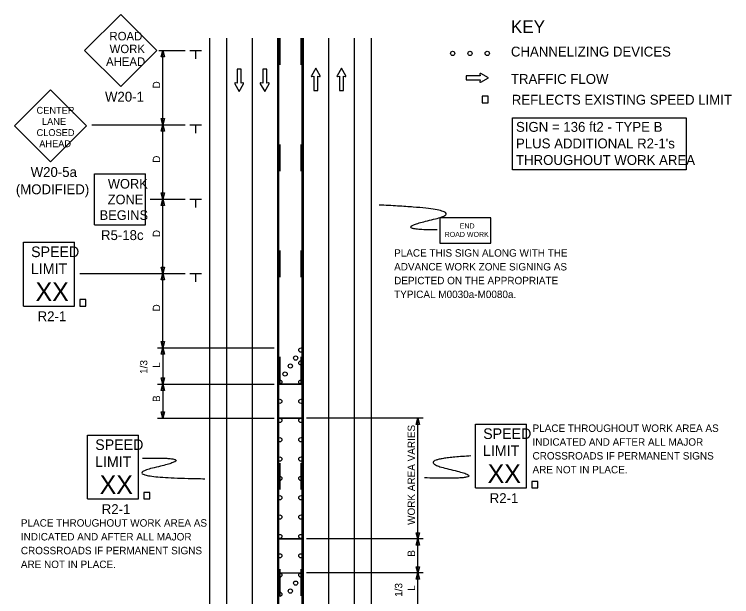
# Model space of a CAD drawing. Extents: x 16739 to 18482, y 7218 to 8206.
# Drawn here: x 16739 to 17415, y 7658 to 8206 of the extents above; entities that cross this region are included whole.
import ezdxf

# ---------------------------------------------------------------- set-up
doc = ezdxf.new("R2010")
doc.units = 0
for name, color, linetype in [('ALI_LEGAL_EX', 7, 'Continuous'), ('MT_SCRATCH_LEVEL_E', 7, 'Continuous'), ('PAVT_EDGE_EX', 7, 'Continuous'), ('TRAFFIC_SIGNS_PR', 7, 'Continuous'), ('TYPICAL_TEXT_DIMEN_EX', 7, 'Continuous'), ('TYPICAL_TEXT_DIMEN_PR', 7, 'Continuous')]:
    doc.layers.add(name, color=color, linetype=linetype)

msp = doc.modelspace()

# ---------------------------------------------------------------- linework, layer by layer
at = {"layer": 'ALI_LEGAL_EX'}
for points in [[(16963.15, 8183.87), (16963.15, 8158.87)], [(17035.15, 8183.87), (17035.15, 8158.87)], [(16963.15, 8083.87), (16963.15, 8058.87)], [(17035.15, 8083.87), (17035.15, 8058.87)], [(16963.15, 7983.87), (16963.15, 7958.87)], [(17035.15, 7983.87), (17035.15, 7958.87)], [(16963.15, 7883.87), (16963.15, 7858.87)], [(17035.15, 7883.87), (17035.15, 7858.87)], [(16963.15, 7783.87), (16963.15, 7758.87)], [(17035.15, 7783.87), (17035.15, 7758.87)], [(16963.15, 7683.87), (16963.15, 7658.87)], [(17035.15, 7683.87), (17035.15, 7658.87)]]:
    msp.add_lwpolyline(points, dxfattribs=at)
at = {"layer": 'MT_SCRATCH_LEVEL_E'}
for p, q in [((16952.82, 8154.76), (16949.08, 8154.76)), ((16949.08, 8154.76), (16949.08, 8141.5)), ((16952.82, 8154.76), (16949.08, 8154.76)), ((16949.08, 8154.76), (16949.08, 8141.5)), ((16952.82, 8141.5), (16952.82, 8154.76)), ((16952.82, 8141.5), (16952.82, 8154.76)), ((16976.89, 8154.76), (16973.15, 8154.76)), ((16973.15, 8154.76), (16973.15, 8141.5)), ((16976.89, 8154.76), (16973.15, 8154.76)), ((16973.15, 8154.76), (16973.15, 8141.5)), ((16976.89, 8141.5), (16976.89, 8154.76)), ((16976.89, 8141.5), (16976.89, 8154.76)), ((17023.09, 8155.7), (17018.98, 8148.46)), ((17023.09, 8155.7), (17018.98, 8148.46)), ((17027.24, 8148.46), (17023.09, 8155.7)), ((17027.24, 8148.46), (17023.09, 8155.7)), ((17047.26, 8155.7), (17043.15, 8148.46)), ((17047.26, 8155.7), (17043.15, 8148.46)), ((17051.4, 8148.46), (17047.26, 8155.7)), ((17051.4, 8148.46), (17047.26, 8155.7)), ((17019.46, 8147.78), (17021.24, 8148.1)), ((17019.46, 8147.78), (17021.24, 8148.1)), ((17021.24, 8148.1), (17021.24, 8134.84)), ((17021.24, 8148.1), (17021.24, 8134.84)), ((17024.98, 8134.84), (17024.98, 8148.1)), ((17024.98, 8148.1), (17026.76, 8147.78)), ((17024.98, 8134.84), (17024.98, 8148.1)), ((17024.98, 8148.1), (17026.76, 8147.78)), ((17043.63, 8147.78), (17045.41, 8148.1)), ((17043.63, 8147.78), (17045.41, 8148.1)), ((17045.41, 8148.1), (17045.41, 8134.84)), ((17045.41, 8148.1), (17045.41, 8134.84)), ((17049.15, 8134.84), (17049.15, 8148.1)), ((17049.15, 8148.1), (17050.93, 8147.78)), ((17049.15, 8134.84), (17049.15, 8148.1)), ((17049.15, 8148.1), (17050.93, 8147.78)), ((17178.02, 8148.4), (17164.76, 8148.4)), ((17164.76, 8148.4), (17164.76, 8144.66)), ((17178.02, 8148.4), (17164.76, 8148.4)), ((17164.76, 8148.4), (17164.76, 8144.66)), ((17177.7, 8150.17), (17178.02, 8148.4)), ((17177.7, 8150.17), (17178.02, 8148.4)), ((17185.63, 8146.55), (17178.39, 8150.66)), ((17185.63, 8146.55), (17178.39, 8150.66)), ((17178.39, 8142.4), (17185.63, 8146.55)), ((17178.39, 8142.4), (17185.63, 8146.55)), ((16946.82, 8141.13), (16950.97, 8133.89)), ((16946.82, 8141.13), (16950.97, 8133.89)), ((16949.08, 8141.5), (16947.3, 8141.82)), ((16949.08, 8141.5), (16947.3, 8141.82)), ((16950.97, 8133.89), (16955.08, 8141.13)), ((16950.97, 8133.89), (16955.08, 8141.13)), ((16954.6, 8141.82), (16952.82, 8141.5)), ((16954.6, 8141.82), (16952.82, 8141.5)), ((16970.9, 8141.13), (16975.04, 8133.89)), ((16970.9, 8141.13), (16975.04, 8133.89)), ((16973.15, 8141.5), (16971.37, 8141.82)), ((16973.15, 8141.5), (16971.37, 8141.82)), ((16975.04, 8133.89), (16979.15, 8141.13)), ((16975.04, 8133.89), (16979.15, 8141.13)), ((16978.67, 8141.82), (16976.89, 8141.5)), ((16978.67, 8141.82), (16976.89, 8141.5)), ((17164.76, 8144.66), (17178.02, 8144.66)), ((17164.76, 8144.66), (17178.02, 8144.66)), ((17178.02, 8144.66), (17177.7, 8142.88)), ((17178.02, 8144.66), (17177.7, 8142.88)), ((17021.24, 8134.84), (17024.98, 8134.84)), ((17021.24, 8134.84), (17024.98, 8134.84)), ((17045.41, 8134.84), (17049.15, 8134.84)), ((17045.41, 8134.84), (17049.15, 8134.84))]:
    msp.add_line(p, q, dxfattribs=at)
for centre, start, end in [((17019.38, 8148.24), 150.42484, 279.96381), ((17019.38, 8148.24), 150.42484, 279.96381), ((17026.83, 8148.24), 260.03619, 29.77312), ((17026.83, 8148.24), 260.03619, 29.77312), ((17043.55, 8148.24), 150.42484, 279.96381), ((17043.55, 8148.24), 150.42484, 279.96381), ((17051, 8148.24), 260.03619, 29.77312), ((17051, 8148.24), 260.03619, 29.77312), ((17178.16, 8150.25), 60.42484, 189.96381), ((17178.16, 8150.25), 60.42484, 189.96381), ((16947.23, 8141.36), 80.03619, 209.77312), ((16947.23, 8141.36), 80.03619, 209.77312), ((16954.67, 8141.36), 330.42484, 99.96381), ((16954.67, 8141.36), 330.42484, 99.96381), ((16971.3, 8141.36), 80.03619, 209.77312), ((16971.3, 8141.36), 80.03619, 209.77312), ((16978.75, 8141.36), 330.42484, 99.96381), ((16978.75, 8141.36), 330.42484, 99.96381), ((17178.16, 8142.81), 170.03619, 299.77312), ((17178.16, 8142.81), 170.03619, 299.77312)]:
    msp.add_arc(centre, 0.463, start, end, dxfattribs=at)
at = {"layer": 'PAVT_EDGE_EX'}
for p, q in [((16923.15, 8183.87), (16923.15, 7354.69)), ((16939.15, 8183.87), (16939.15, 7354.69)), ((16963.15, 8183.87), (16963.15, 7354.69)), ((16987.15, 8183.87), (16987.15, 7354.69)), ((16988.15, 8183.87), (16988.15, 7354.69)), ((17010.15, 8183.87), (17010.15, 7354.69)), ((17011.15, 8183.87), (17011.15, 7354.69)), ((17035.15, 8183.87), (17035.15, 7354.69)), ((17059.15, 8183.87), (17059.15, 7354.69)), ((17075.15, 8183.87), (17075.15, 7354.69)), ((16987.15, 7858.2), (17011.15, 7858.2)), ((17011.15, 7858.2), (16987.15, 7858.2)), ((16987.15, 7858.2), (16987.15, 7826.14)), ((17011.15, 7826.14), (17011.15, 7858.2)), ((17011.15, 7826.14), (16987.15, 7826.14)), ((16987.15, 7826.14), (16987.15, 7712.42)), ((16987.15, 7826.14), (17011.15, 7826.14)), ((16987.15, 7826.14), (17011.15, 7826.14)), ((16987.15, 7826.14), (17011.15, 7826.14)), ((17011.15, 7712.42), (17011.15, 7826.14)), ((16987.15, 7712.42), (17011.15, 7712.42)), ((16987.15, 7712.42), (17011.15, 7712.42)), ((17011.15, 7712.42), (16987.15, 7712.42)), ((16987.15, 7712.42), (16987.15, 7680.36)), ((17011.15, 7680.36), (17011.15, 7712.42)), ((16987.15, 7680.36), (17011.15, 7680.36)), ((16987.15, 7680.36), (17011.15, 7680.36))]:
    msp.add_line(p, q, dxfattribs=at)
for points in [[(16989.15, 8183.87), (16989.15, 8158.87)], [(17009.15, 8183.87), (17009.15, 8158.87)], [(16989.15, 8083.87), (16989.15, 8058.87)], [(17009.15, 8083.87), (17009.15, 8058.87)], [(16989.15, 7983.87), (16989.15, 7958.87)], [(17009.15, 7983.87), (17009.15, 7958.87)], [(16989.15, 7883.87), (16989.15, 7858.87)], [(17009.15, 7883.87), (17009.15, 7858.87)], [(16989.15, 7783.87), (16989.15, 7758.87)], [(17009.15, 7783.87), (17009.15, 7758.87)], [(16989.15, 7683.87), (16989.15, 7658.87)], [(17009.15, 7683.87), (17009.15, 7658.87)]]:
    msp.add_lwpolyline(points, dxfattribs=at)
at = {"layer": 'TRAFFIC_SIGNS_PR'}
for p, q in [((16839.46, 8206.42), (16805.51, 8172.48)), ((16873.4, 8172.48), (16839.46, 8206.42)), ((16805.51, 8172.48), (16839.46, 8138.54)), ((16839.46, 8138.54), (16873.4, 8172.48)), ((16773.26, 8135.48), (16739.32, 8101.54)), ((16807.2, 8101.54), (16773.26, 8135.48)), ((16739.32, 8101.54), (16773.26, 8067.59)), ((16773.26, 8067.59), (16807.2, 8101.54)), ((16814.89, 8008.16), (16814.89, 8056.16)), ((16814.89, 8056.16), (16862.89, 8056.16)), ((16862.89, 8008.16), (16862.89, 8056.16)), ((16814.89, 8008.16), (16862.89, 8008.16)), ((16747.89, 7991.73), (16795.89, 7991.73)), ((16747.89, 7931.73), (16747.89, 7991.73)), ((16795.89, 7931.73), (16795.89, 7991.73)), ((16747.89, 7931.73), (16795.89, 7931.73)), ((17173.54, 7820.47), (17221.54, 7820.47)), ((17173.54, 7760.47), (17173.54, 7820.47)), ((17221.54, 7760.47), (17221.54, 7820.47)), ((16808.27, 7810.1), (16856.27, 7810.1)), ((16808.27, 7750.1), (16808.27, 7810.1)), ((16856.27, 7750.1), (16856.27, 7810.1)), ((17173.54, 7760.47), (17221.54, 7760.47)), ((16808.27, 7750.1), (16856.27, 7750.1))]:
    msp.add_line(p, q, dxfattribs=at)
for points in [[(17179.71, 8123.17), (17185.3, 8123.17), (17185.3, 8129.34), (17179.71, 8129.34)], [(17139.95, 7990.83), (17187.95, 7990.83), (17187.95, 8014.83), (17139.95, 8014.83)], [(16800.9, 7931.73), (16806.5, 7931.73), (16806.5, 7937.9), (16800.9, 7937.9)], [(17226.56, 7760.47), (17232.15, 7760.47), (17232.15, 7766.64), (17226.56, 7766.64)], [(16861.28, 7750.1), (16866.88, 7750.1), (16866.88, 7756.28), (16861.28, 7756.28)]]:
    msp.add_lwpolyline(points, close=True, dxfattribs=at)
for centre in [(17152, 8169.65), (17168.3, 8169.65), (17184.6, 8169.65), (17009.13, 7890.24), (17004.16, 7882.72), (16999.19, 7875.22), (17009.13, 7878.21), (16994.22, 7867.72), (16989.25, 7860.21), (17009.13, 7860.21), (16989.25, 7842.02), (17009.13, 7842.02), (16989.25, 7824.02), (17009.13, 7824.02), (16989.25, 7805.81), (17009.13, 7805.81), (16989.25, 7787.59), (17009.13, 7787.59), (16989.25, 7769.38), (17009.13, 7769.38), (16989.25, 7751.16), (17009.13, 7751.16), (16989.25, 7732.95), (17009.13, 7732.95), (16989.25, 7714.73), (17009.13, 7714.73), (16989.25, 7696.52), (17009.13, 7696.52), (16989.25, 7678.31), (17009.13, 7678.31), (17004.16, 7670.79), (16989.25, 7660.31), (16999.19, 7663.29)]:
    msp.add_circle(centre, 2, dxfattribs=at)
for points in [[(17137.31, 8003.38), (17090.07, 8003.38), (17175.09, 8022.73), (17082.79, 8026.8)], [(16859.89, 7788.48), (16915.71, 7789.66), (16830.69, 7770.31), (16918.68, 7769.09)], [(17169.18, 7790.54), (17108.58, 7787.16), (17193.6, 7767.82), (17125.41, 7769.9)]]:
    msp.add_open_spline(points, degree=2, dxfattribs=at)
at = {"layer": 'TYPICAL_TEXT_DIMEN_EX'}
msp.add_lwpolyline([(17208.29, 8108.9), (17371.94, 8108.9), (17371.94, 8059.86), (17208.29, 8059.86)], close=True, dxfattribs=at)
at = {"layer": 'TYPICAL_TEXT_DIMEN_PR'}
for p, q in [((16875.49, 8172.39), (16900.15, 8172.39)), ((16877.58, 8166.53), (16879.15, 8172.39)), ((16879.15, 8102.39), (16879.15, 8172.39)), ((16879.15, 8172.39), (16880.72, 8166.53)), ((16904.4, 8172.39), (16915.65, 8172.39)), ((16910.03, 8172.39), (16910.03, 8164.61)), ((16879.15, 8166.53), (16877.58, 8166.53)), ((16880.72, 8166.53), (16879.15, 8166.53)), ((16879.15, 8102.39), (16877.58, 8108.25)), ((16877.58, 8108.25), (16879.15, 8108.25)), ((16879.15, 8108.25), (16880.72, 8108.25)), ((16880.72, 8108.25), (16879.15, 8102.39)), ((16812.23, 8102.39), (16900.15, 8102.39)), ((16877.58, 8096.53), (16879.15, 8102.39)), ((16879.15, 8102.39), (16880.72, 8096.53)), ((16879.15, 8032.39), (16879.15, 8102.39)), ((16904.4, 8102.39), (16915.65, 8102.39)), ((16910.03, 8102.39), (16910.03, 8094.61)), ((16879.15, 8096.53), (16877.58, 8096.53)), ((16880.72, 8096.53), (16879.15, 8096.53)), ((16879.15, 8032.39), (16877.58, 8038.25)), ((16877.58, 8038.25), (16879.15, 8038.25)), ((16879.15, 8038.25), (16880.72, 8038.25)), ((16880.72, 8038.25), (16879.15, 8032.39)), ((16867.3, 8032.39), (16900.15, 8032.39)), ((16877.58, 8026.53), (16879.15, 8032.39)), ((16879.15, 7962.39), (16879.15, 8032.39)), ((16879.15, 8032.39), (16880.72, 8026.53)), ((16904.4, 8032.39), (16915.65, 8032.39)), ((16910.03, 8032.39), (16910.03, 8024.61)), ((16879.15, 8026.53), (16877.58, 8026.53)), ((16880.72, 8026.53), (16879.15, 8026.53)), ((16879.15, 7962.39), (16877.58, 7968.25)), ((16877.58, 7968.25), (16879.15, 7968.25)), ((16879.15, 7968.25), (16880.72, 7968.25)), ((16880.72, 7968.25), (16879.15, 7962.39)), ((16800.86, 7962.39), (16900.15, 7962.39)), ((16877.58, 7956.53), (16879.15, 7962.39)), ((16879.15, 7956.53), (16877.58, 7956.53)), ((16879.15, 7892.39), (16879.15, 7962.39)), ((16879.15, 7962.39), (16880.72, 7956.53)), ((16880.72, 7956.53), (16879.15, 7956.53)), ((16904.4, 7962.39), (16915.65, 7962.39)), ((16910.03, 7962.39), (16910.03, 7954.61)), ((16879.15, 7892.39), (16877.58, 7898.25)), ((16877.58, 7898.25), (16879.15, 7898.25)), ((16879.15, 7898.25), (16880.72, 7898.25)), ((16880.72, 7898.25), (16879.15, 7892.39)), ((16874.15, 7892.39), (16983.85, 7892.39)), ((16877.58, 7886.53), (16879.15, 7892.39)), ((16879.15, 7892.39), (16879.15, 7858.2)), ((16879.15, 7892.39), (16880.72, 7886.53)), ((16879.15, 7886.53), (16877.58, 7886.53)), ((16880.72, 7886.53), (16879.15, 7886.53)), ((16879.15, 7858.2), (16877.58, 7864.06)), ((16877.58, 7864.06), (16879.15, 7864.06)), ((16879.15, 7864.06), (16880.72, 7864.06)), ((16880.72, 7864.06), (16879.15, 7858.2)), ((16874.15, 7858.2), (16983.85, 7858.2)), ((16877.58, 7852.34), (16879.15, 7858.2)), ((16879.15, 7858.2), (16879.15, 7826.14)), ((16879.15, 7858.2), (16880.72, 7852.34)), ((16879.15, 7852.34), (16877.58, 7852.34)), ((16880.72, 7852.34), (16879.15, 7852.34)), ((16879.15, 7826.14), (16877.58, 7832)), ((16877.58, 7832), (16879.15, 7832)), ((16879.15, 7832), (16880.72, 7832)), ((16880.72, 7832), (16879.15, 7826.14)), ((16874.15, 7826.14), (16983.85, 7826.14)), ((17124.15, 7826.14), (17014.45, 7826.14)), ((17117.58, 7820.28), (17119.15, 7826.14)), ((17119.15, 7712.42), (17119.15, 7826.14)), ((17119.15, 7826.14), (17120.72, 7820.28)), ((17119.15, 7820.28), (17117.58, 7820.28)), ((17120.72, 7820.28), (17119.15, 7820.28)), ((17119.15, 7712.42), (17117.58, 7718.28)), ((17117.58, 7718.28), (17119.15, 7718.28)), ((17119.15, 7718.28), (17120.72, 7718.28)), ((17120.72, 7718.28), (17119.15, 7712.42)), ((17124.15, 7712.42), (17014.45, 7712.42)), ((17117.58, 7706.56), (17119.15, 7712.42)), ((17119.15, 7706.56), (17117.58, 7706.56)), ((17119.15, 7680.36), (17119.15, 7712.42)), ((17119.15, 7712.42), (17120.72, 7706.56)), ((17120.72, 7706.56), (17119.15, 7706.56)), ((17119.15, 7680.36), (17117.58, 7686.22)), ((17117.58, 7686.22), (17119.15, 7686.22)), ((17119.15, 7686.22), (17120.72, 7686.22)), ((17120.72, 7686.22), (17119.15, 7680.36)), ((17124.15, 7680.36), (17014.45, 7680.36)), ((17117.58, 7674.5), (17119.15, 7680.36)), ((17119.15, 7646.17), (17119.15, 7680.36)), ((17119.15, 7680.36), (17120.72, 7674.5)), ((17119.15, 7674.5), (17117.58, 7674.5)), ((17120.72, 7674.5), (17119.15, 7674.5))]:
    msp.add_line(p, q, dxfattribs=at)

# ---------------------------------------------------------------- texts
at = {"layer": 'TRAFFIC_SIGNS_PR'}
for s, height, p in [('ROAD', 8, (16828.88, 8181.9)), ('WORK', 8, (16829.02, 8169.9)), ('AHEAD', 8, (16825.66, 8157.9)), ('W20-1', 9.3, (16824.67, 8124.24)), ('CENTER', 6.5, (16760.23, 8112.79)), ('LANE', 6.5, (16765.33, 8102.29)), ('CLOSED', 6.5, (16760.24, 8091.79)), ('AHEAD', 6.5, (16762.77, 8081.29)), ('W20-5a', 9.3, (16754.69, 8053.29)), ('WORK', 9.021, (16827.39, 8042.37)), ('(MODIFIED)', 9.3, (16740.75, 8036.99)), ('ZONE', 9.021, (16827.24, 8027.6)), ('BEGINS', 9.021, (16819.66, 8012.84)), ('R5-18c', 9.3, (16820.91, 7993.86)), ('END', 4.789, (17158.7, 8004.75)), ('ROAD WORK', 4.789, (17144.46, 7996.77)), ('SPEED', 10, (16755.1, 7977.8)), ('PLACE THIS SIGN ALONG WITH THE', 7, (17096.89, 7978.23)), ('LIMIT', 10, (16754.89, 7961.8)), ('ADVANCE WORK ZONE SIGNING AS', 7, (17096.89, 7965.23)), ('DEPICTED ON THE APPROPRIATE', 7, (17096.89, 7952.23)), ('XX', 17.538, (16759.28, 7936.42)), ('TYPICAL M0030a-M0080a.', 7, (17096.89, 7939.23)), ('R2-1', 9.3, (16761.23, 7917.43)), ('SPEED', 10, (17180.75, 7806.54)), ('PLACE THROUGHOUT WORK AREA AS', 7, (17227.21, 7813.18)), ('INDICATED AND AFTER ALL MAJOR', 7, (17227.21, 7800.18)), ('SPEED', 10, (16815.48, 7796.18)), ('LIMIT', 10, (17180.55, 7790.54)), ('CROSSROADS IF PERMANENT SIGNS', 7, (17227.21, 7787.18)), ('LIMIT', 10, (16815.27, 7780.18)), ('XX', 17.538, (17184.93, 7765.16)), ('ARE NOT IN PLACE.', 7, (17227.21, 7774.18)), ('XX', 17.538, (16819.66, 7754.8)), ('R2-1', 9.3, (17186.88, 7746.16)), ('R2-1', 9.3, (16821.61, 7735.8)), ('PLACE THROUGHOUT WORK AREA AS', 7, (16745.46, 7723.97)), ('INDICATED AND AFTER ALL MAJOR', 7, (16745.46, 7710.97)), ('CROSSROADS IF PERMANENT SIGNS', 7, (16745.46, 7697.97)), ('ARE NOT IN PLACE.', 7, (16745.46, 7684.97))]:
    msp.add_text(s, height=height, dxfattribs=at).set_placement(p)
at = {"layer": 'TYPICAL_TEXT_DIMEN_EX'}
for s, height, p in [('KEY', 12, (17206.84, 8188.76)), ('CHANNELIZING DEVICES', 9.3, (17206.84, 8166.71)), ('TRAFFIC FLOW', 9.3, (17206.84, 8140.91)), ('REFLECTS EXISTING SPEED LIMIT', 9.3, (17207.66, 8121.33)), ('SIGN = 136 ft2 - TYPE B', 9.3, (17211.63, 8095.79)), ("PLUS ADDITIONAL R2-1's", 9.3, (17211.63, 8080.19)), ('THROUGHOUT WORK AREA', 9.3, (17211.63, 8064.59))]:
    msp.add_text(s, height=height, dxfattribs=at).set_placement(p)
at = {"layer": 'TYPICAL_TEXT_DIMEN_PR'}
for s, p in [('D', (16876.59, 8136.61)), ('D', (16876.59, 8066.61)), ('D', (16876.59, 7996.61)), ('D', (16876.59, 7926.61)), ('1/3', (16864.59, 7867.83)), ('L', (16876.59, 7873.62)), ('B', (16876.59, 7841.41)), ('WORK AREA VARIES', (17116.59, 7725.64)), ('B', (17116.59, 7695.62)), ('1/3', (17104.59, 7657.86)), ('L', (17116.59, 7663.65))]:
    msp.add_text(s, height=7, rotation=90, dxfattribs=at).set_placement(p)

doc.saveas('drawing.dxf')
